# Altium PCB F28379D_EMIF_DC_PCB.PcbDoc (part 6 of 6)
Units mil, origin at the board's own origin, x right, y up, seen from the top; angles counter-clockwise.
Board outline 3000 x 1480 mil, 6 copper layers (Top Layer, Signal Layer 1, Signal Layer 2, Signal Layer 3, Signal Layer 4, Bottom Layer), stack 61.4 mil thick; 51 components, 68 nets, 414 pads, 205 vias.
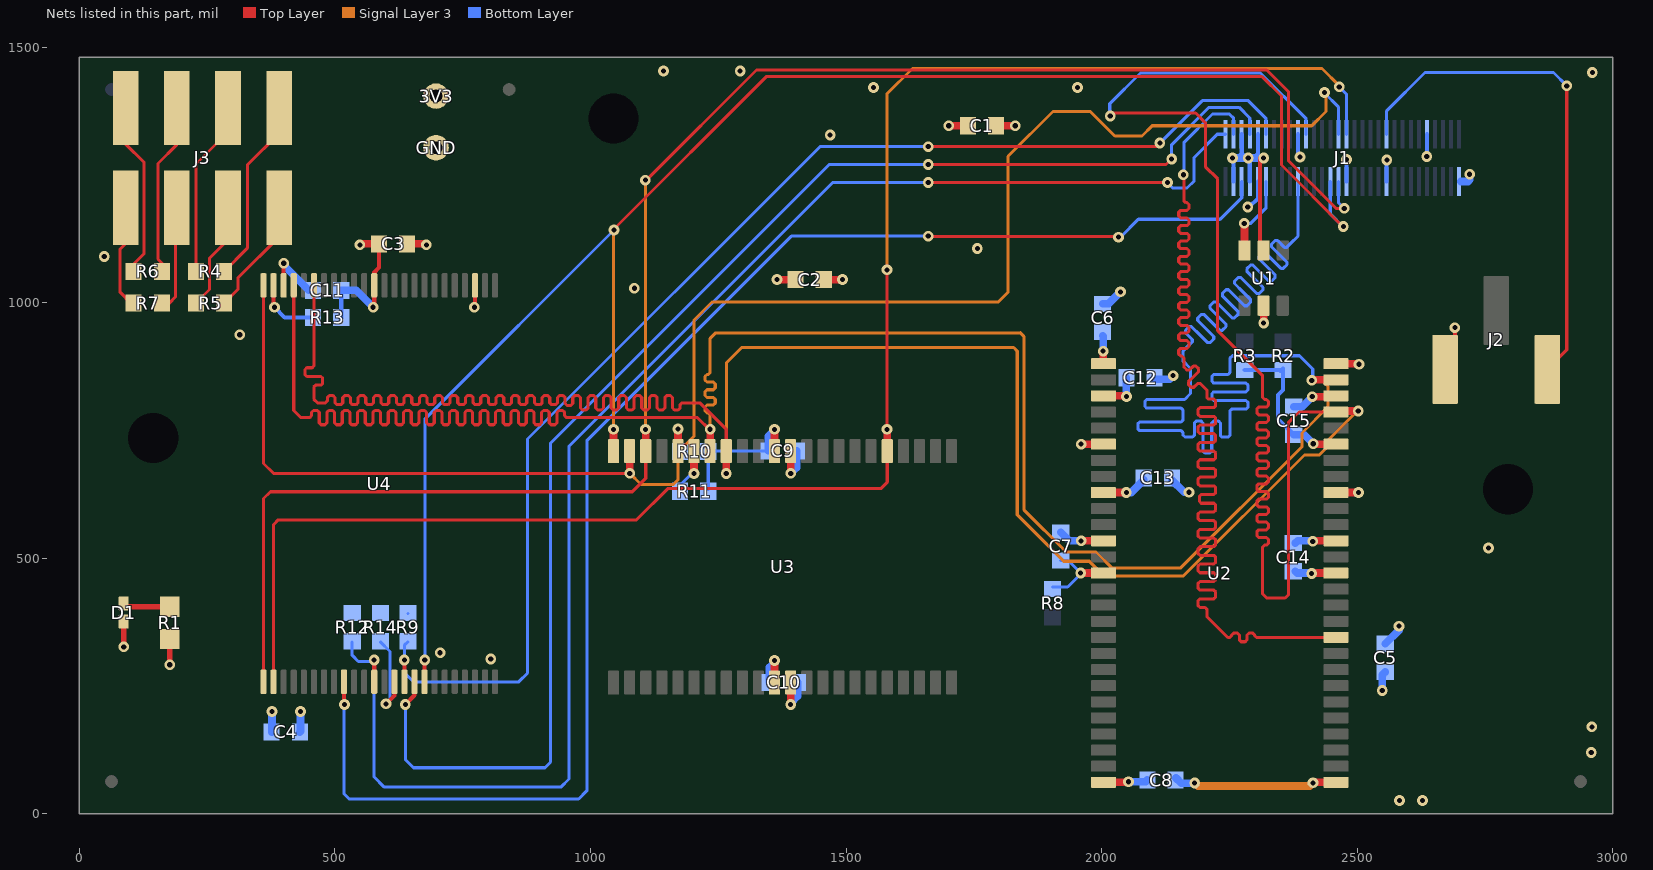
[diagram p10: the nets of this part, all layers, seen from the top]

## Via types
v1: diameter 21, hole 10, Top Layer to Bottom Layer, 204 vias
v2: diameter 20, hole 10, Top Layer to Bottom Layer, 1 vias

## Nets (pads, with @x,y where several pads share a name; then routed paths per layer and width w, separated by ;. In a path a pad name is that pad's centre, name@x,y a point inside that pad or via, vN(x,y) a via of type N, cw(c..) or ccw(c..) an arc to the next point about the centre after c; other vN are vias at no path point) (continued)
EM_D14: J1.40@2400.13,1329.26 U2.51 U3.37 U4.43 | length 6462.4
  Top Layer w6: U4.43@459.05,1033.8 459.05,967 459.05,875.9 455.65,872.5 445.25,872.5 441.85,869.1 441.85,858.9 445.25,855.5 459.05,855.5 472.85,855.5 476.25,852.1 476.25,841.9 472.85,838.5 462.45,838.5 459.05,835.1 459.05,821.5 459.05,813 459.05,811 466.05,804 478,804 481.75,804 485.5,807.75 485.5,814.25 489.25,818 496.75,818 500.5,814.25 500.5,804 504.23,800.26 511.77,800.26 515.5,804 515.5,814.25 519.25,818 526.75,818 530.5,814.25 530.5,804 534.23,800.26 541.77,800.26 545.5,804 545.5,814.25 549.25,818 556.75,818 560.5,814.25 560.5,804 564.23,800.26 571.77,800.26 575.5,804 575.5,814.25 579.25,818 586.75,818 590.5,814.25 590.5,804 594.23,800.26 601.77,800.26 605.5,804 605.5,814.25 609.25,818 616.75,818 620.5,814.25 620.5,804 624.23,800.26 631.77,800.26 635.5,804 635.5,814.25 639.25,818 646.75,818 650.5,814.25 650.5,804 654.23,800.26 661.77,800.26 665.5,804 665.5,814.25 669.25,818 676.75,818 680.5,814.25 680.5,804 684.23,800.26 691.77,800.26 695.5,804 695.5,814.25 699.25,818 706.75,818 710.5,814.25 710.5,804 714.23,800.26 721.77,800.26 725.5,804 725.5,814.25 729.25,818 736.75,818 740.5,814.25 740.5,804 744.23,800.26 751.77,800.26 755.5,804 755.5,814.25 759.25,818 766.75,818 770.5,814.25 770.5,804 774.23,800.26 781.77,800.26 785.5,804 785.5,814.25 789.25,818 796.75,818 800.5,814.25 800.5,804 804.23,800.26 811.77,800.26 815.5,804 815.5,814.25 819.25,818 826.75,818 830.5,814.25 830.5,804 834.23,800.26 841.77,800.26 845.5,804 845.5,814.25 849.25,818 856.75,818 860.5,814.25 860.5,804 864.23,800.26 871.77,800.26 875.5,804 875.5,814.25 879.25,818 886.75,818 890.5,814.25 890.5,804 894.23,800.26 901.77,800.26 905.5,804 905.5,814.25 909.25,818 916.75,818 920.5,814.25 920.5,804 924.23,800.26 931.77,800.26 935.5,804 935.5,814.25 939.25,818 946.75,818 950.5,814.25 950.5,804 950.5,802.58 954.25,798.83 961.75,798.83 965.5,802.58 965.5,804 965.5,814.25 969.25,818 976.75,818 980.5,814.25 980.5,804 980.5,793.75 984.25,790 991.75,790 995.5,793.75 995.5,804 995.5,814.25 999.25,818 1006.75,818 1010.5,814.25 1010.5,804 1010.5,793.75 1014.25,790 1021.75,790 1025.5,793.75 1025.5,804 1025.5,814.25 1029.25,818 1036.75,818 1040.5,814.25 1040.5,804 1040.5,793.75 1044.25,790 1051.75,790 1055.5,793.75 1055.5,804 1055.5,814.25 1059.25,818 1066.75,818 1070.5,814.25 1070.5,804 1070.5,793.75 1074.25,790 1081.75,790 1085.5,793.75 1085.5,804 1085.5,814.25 1089.25,818 1096.75,818 1100.5,814.25 1100.5,804 1100.5,793.75 1104.25,790 1111.75,790 1115.5,793.75 1115.5,804 1115.5,814.25 1119.25,818 1126.75,818 1130.5,814.25 1130.5,804 1130.5,793.75 1134.25,790 1141.75,790 1145.5,793.75 1145.5,804 1145.5,814.25 1149.25,818 1156.75,818 1160.5,814.25 1160.5,804 1160.5,793.75 1164.25,790 1171.75,790 1175.5,793.75 1175.5,800.25 1179.25,804 1206,804 1214,804 1265.76,752.24 U3.37@1265.76,709.38 ; v1@2016,1366 2021,1371 2184,1371 2203,1352 2203,1266 2227,1242 2227,945 2315,857 2315,818 2315,814.25 2318.75,810.5 2322.5,810.5 2326.25,806.75 2326.25,799.25 2322.5,795.5 2315,795.5 2307.5,795.5 2303.75,791.75 2303.75,784.25 2307.5,780.5 2315,780.5 2322.5,780.5 2326.25,776.75 2326.25,769.25 2322.5,765.5 2315,765.5 2307.5,765.5 2303.75,761.75 2303.75,754.25 2307.5,750.5 2315,750.5 2322.5,750.5 2326.25,746.75 2326.25,739.25 2322.5,735.5 2315,735.5 2307.5,735.5 2303.75,731.75 2303.75,724.25 2307.5,720.5 2315,720.5 2322.5,720.5 2326.25,716.75 2326.25,709.25 2322.5,705.5 2315,705.5 2307.5,705.5 2303.75,701.75 2303.75,694.25 2307.5,690.5 2315,690.5 2322.5,690.5 2326.25,686.75 2326.25,679.25 2322.5,675.5 2315,675.5 2307.5,675.5 2303.75,671.75 2303.75,664.25 2307.5,660.5 2315,660.5 2322.5,660.5 2326.25,656.75 2326.25,649.25 2322.5,645.5 2315,645.5 2307.5,645.5 2303.75,641.75 2303.75,634.25 2307.5,630.5 2315,630.5 2322.5,630.5 2326.25,626.75 2326.25,619.25 2322.5,615.5 2315,615.5 2307.5,615.5 2303.75,611.75 2303.75,604.25 2307.5,600.5 2315,600.5 2322.5,600.5 2326.25,596.75 2326.25,589.25 2322.5,585.5 2315,585.5 2307.5,585.5 2303.75,581.75 2303.75,574.25 2307.5,570.5 2315,570.5 2322.5,570.5 2326.25,566.75 2326.25,559.25 2322.5,555.5 2315,555.5 2307.5,555.5 2303.75,551.75 2303.75,544.25 2307.5,540.5 2315,540.5 2322.5,540.5 2326.25,536.75 2326.25,529.25 2322.5,525.5 2318.75,525.5 2315,521.75 2315,445 2315,430 2323,422 2359,422 2366,429 2366,765.92 2386.04,785.96 U2.51@2458.36,785.96
  Top Layer w15: v1(1265.76,665.76) U3.37@1265.76,709.38 ; U2.51@2458.36,785.96 2460.4,788 v1@2500,788
  Signal Layer 3 w6: v1@1265.76,674.76 1266,675 1266,882 1296,912 1828,912 1835,905 1835,585 1926,494 1976,494 2005,465 2160,465 2397,702 2426,702 2439,715 2439,727 v1@2500,788
  Bottom Layer w6: v1@2016,1366 2016,1389 2076,1449 2311,1449 2400.13,1359.87 J1.40@2400.13,1329.26
  other v1: 2502,788 2017,1365
EM_D15: J1.41@2384.39,1236.74 U2.53 U3.38 U4.45 | length 6511.9
  Top Layer w6: U4.45@419.68,1033.8 419.68,789 433.68,775 447,775 450.75,775 454.5,778.75 454.5,785.25 458.25,789 465.75,789 469.5,785.25 469.5,775 469.5,764.75 473.25,761 480.75,761 484.5,764.75 484.5,775 484.5,785.25 488.25,789 495.75,789 499.5,785.25 499.5,775 499.5,764.75 503.25,761 510.75,761 514.5,764.75 514.5,775 514.5,785.25 518.25,789 525.75,789 529.5,785.25 529.5,775 529.5,764.75 533.25,761 540.75,761 544.5,764.75 544.5,775 544.5,785.25 548.25,789 555.75,789 559.5,785.25 559.5,775 559.5,764.75 563.25,761 570.75,761 574.5,764.75 574.5,775 574.5,785.25 578.25,789 585.75,789 589.5,785.25 589.5,775 589.5,764.75 593.25,761 600.75,761 604.5,764.75 604.5,775 604.5,785.25 608.25,789 615.75,789 619.5,785.25 619.5,775 619.5,764.75 623.25,761 630.75,761 634.5,764.75 634.5,775 634.5,785.25 638.25,789 645.75,789 649.5,785.25 649.5,775 649.5,764.75 653.25,761 660.75,761 664.5,764.75 664.5,775 664.5,785.25 668.25,789 675.75,789 679.5,785.25 679.5,775 679.5,764.75 683.25,761 690.75,761 694.5,764.75 694.5,775 694.5,785.25 698.25,789 705.75,789 709.5,785.25 709.5,775 709.5,764.75 713.25,761 720.75,761 724.5,764.75 724.5,775 724.5,785.25 728.25,789 735.75,789 739.5,785.25 739.5,775 739.5,764.75 743.25,761 750.75,761 754.5,764.75 754.5,775 754.5,785.25 758.25,789 765.75,789 769.5,785.25 769.5,775 769.5,764.75 773.25,761 780.75,761 784.5,764.75 784.5,775 784.5,785.25 788.25,789 795.75,789 799.5,785.25 799.5,775 799.5,764.75 803.25,761 810.75,761 814.5,764.75 814.5,775 814.5,785.25 818.25,789 825.75,789 829.5,785.25 829.5,775 829.5,764.75 833.25,761 840.75,761 844.5,764.75 844.5,775 844.5,785.25 848.25,789 855.75,789 859.5,785.25 859.5,775 859.5,764.75 863.25,761 870.75,761 874.5,764.75 874.5,775 874.5,785.25 878.25,789 885.75,789 889.5,785.25 889.5,775 889.5,764.75 893.25,761 900.75,761 904.5,764.75 904.5,775 904.5,785.25 908.25,789 915.75,789 919.5,785.25 919.5,775 919.5,764.75 923.25,761 930.75,761 934.5,764.75 934.5,775 934.5,785.25 938.25,789 945.75,789 949.5,785.25 949.5,778.75 953.25,775 1026,775 1209.54,775 v1@1234.27,750.27
  Top Layer w15: U3.38@1234.27,709.38 v1@1234.27,744.27 ; v1(2411.05,847.95) 2412.05,848.95 U2.53@2458.36,848.95
  Signal Layer 3 w6: v1@1234.27,744.27 v1(1234.27,752.27) 1234.27,777 1234.27,780.75 1230.52,784.5 1228.02,784.5 1224.27,788.25 1224.27,795.75 1228.02,799.5 1234.27,799.5 1240.52,799.5 1244.27,803.25 1244.27,810.75 1240.52,814.5 1234.27,814.5 1228.02,814.5 1224.27,818.25 1224.27,825.75 1228.02,829.5 1234.27,829.5 1240.52,829.5 1244.27,833.25 1244.27,840.75 1240.52,844.5 1234.27,844.5 1228.02,844.5 1224.27,848.25 1224.27,855.75 1228.02,859.5 1230.52,859.5 1234.27,863.25 1234.27,918 1234.27,930 1245,940.73 1840.73,940.73 1841,941 1848,934 1848,595 1931,512 1989,512 2020,481 2155,481 2392,718 2392,745 2443,796 2443,836 2430.05,848.95 2412.05,848.95 v1(2411.05,847.95)
  Bottom Layer w6: J1.41@2384.39,1236.74 2384.39,1130 2369.19,1114.81 2362.42,1108.03 2357.61,1108.03 2344.33,1121.32 2339.52,1121.32 2332.31,1114.11 2332.31,1109.3 2347.99,1093.61 2362.67,1078.93 2362.67,1074.12 2355.46,1066.91 2350.65,1066.91 2335.97,1081.59 2320.29,1097.28 2315.48,1097.28 2308.26,1090.06 2308.26,1085.26 2323.95,1069.57 2339.64,1053.88 2339.64,1049.07 2332.43,1041.86 2327.62,1041.86 2311.93,1057.55 2296.24,1073.24 2291.44,1073.24 2284.22,1066.02 2284.22,1061.21 2299.91,1045.53 2315.6,1029.84 2315.6,1025.03 2308.39,1017.82 2303.58,1017.82 2287.89,1033.5 2272.2,1049.19 2267.39,1049.19 2260.18,1041.98 2260.18,1037.17 2275.87,1021.48 2291.56,1005.8 2291.56,1000.99 2284.35,993.77 2279.54,993.77 2263.85,1009.46 2248.16,1025.15 2243.35,1025.15 2236.14,1017.94 2236.14,1013.13 2251.83,997.44 2267.09,982.18 2267.09,977.37 2259.88,970.16 2255.07,970.16 2239.81,985.42 2224.12,1001.11 2219.31,1001.11 2212.1,993.9 2212.1,989.09 2227.79,973.4 2243.48,957.71 2243.48,952.9 2236.26,945.69 2231.45,945.69 2215.77,961.38 2200.08,977.07 2195.27,977.07 2188.06,969.86 2188.06,965.05 2203.74,949.36 2219.43,933.67 2219.43,928.86 2212.22,921.65 2207.41,921.65 2191.72,937.34 2176.04,953.03 2171.23,953.03 2164.01,945.81 2164.01,941.01 2177.3,927.72 2177.3,922.91 2173.69,919.31 2159,904.61 2159,886 2174,871 2174,822 2162.5,810.5 2158.5,810.5 2088.4,810.5 2085,807.1 2085,796.9 2088.4,793.5 2155.6,793.5 2159,790.1 2159,785 2159,774 2159,769.9 2155.6,766.5 2074.4,766.5 2071,763.1 2071,752.9 2074.4,749.5 2155.6,749.5 2159,746.1 2159,741 2163,737 2173,737 2178.1,737 2181.5,740.4 2181.5,764.6 2184.9,768 2195.1,768 2198.5,764.6 2198.5,737 2198.5,709.4 2201.9,706 2212.1,706 2215.5,709.4 2215.5,737 2215.5,764.6 2218.9,768 2229.1,768 2232.5,764.6 2232.5,739.5 2235,737 2248,737 2251,740 2251,783 2251,788.1 2254.4,791.5 2282.6,791.5 2286,794.9 2286,805.1 2282.6,808.5 2251,808.5 2219.4,808.5 2216,811.9 2216,822.1 2219.4,825.5 2251,825.5 2282.6,825.5 2286,828.9 2286,839.1 2282.6,842.5 2251,842.5 2219.4,842.5 2216,845.9 2216,856.1 2219.4,859.5 2247.6,859.5 2251,862.9 2251,876.5 2251,885 2251,891 2256,896 2387,896 2413.05,869.95 v1@2413.05,849.95 ; v1@2409.79,845.69 2413.05,848.95 v1@2413.05,849.95 ; v1(2411.05,847.95) v1@2413.05,849.95
EM_SDCKE: J1.58@2258.4,1329.26 U2.37 | length 2486.2
  Top Layer w6: v1(2160,1250) 2161,1249 2161,1203 2161,1199.25 2164.75,1195.5 2167.25,1195.5 2171,1191.75 2171,1184.25 2167.25,1180.5 2161,1180.5 2154.75,1180.5 2151,1176.75 2151,1169.25 2154.75,1165.5 2161,1165.5 2167.25,1165.5 2171,1161.75 2171,1154.25 2167.25,1150.5 2161,1150.5 2154.75,1150.5 2151,1146.75 2151,1139.25 2154.75,1135.5 2161,1135.5 2167.25,1135.5 2171,1131.75 2171,1124.25 2167.25,1120.5 2161,1120.5 2154.75,1120.5 2151,1116.75 2151,1109.25 2154.75,1105.5 2161,1105.5 2167.25,1105.5 2171,1101.75 2171,1094.25 2167.25,1090.5 2161,1090.5 2154.75,1090.5 2151,1086.75 2151,1079.25 2154.75,1075.5 2161,1075.5 2167.25,1075.5 2171,1071.75 2171,1064.25 2167.25,1060.5 2161,1060.5 2154.75,1060.5 2151,1056.75 2151,1049.25 2154.75,1045.5 2161,1045.5 2167.25,1045.5 2171,1041.75 2171,1034.25 2167.25,1030.5 2161,1030.5 2154.75,1030.5 2151,1026.75 2151,1019.25 2154.75,1015.5 2161,1015.5 2167.25,1015.5 2171,1011.75 2171,1004.25 2167.25,1000.5 2161,1000.5 2154.75,1000.5 2151,996.75 2151,989.25 2154.75,985.5 2161,985.5 2167.25,985.5 2171,981.75 2171,974.25 2167.25,970.5 2161,970.5 2154.75,970.5 2151,966.75 2151,959.25 2154.75,955.5 2161,955.5 2167.25,955.5 2171,951.75 2171,944.25 2167.25,940.5 2161,940.5 2154.75,940.5 2151,936.75 2151,929.25 2154.75,925.5 2161,925.5 2167.25,925.5 2171,921.75 2171,914.25 2167.25,910.5 2161,910.5 2154.75,910.5 2151,906.75 2151,899.25 2154.75,895.5 2157.25,895.5 2161,891.75 2161,880.5 2161,877 2161,874 2164,871 2166.65,868.35 2171.95,868.35 2179.38,875.77 2184.68,875.77 2189.99,870.47 2189.99,865.17 2179.91,855.09 2169.83,845.01 2169.83,839.71 2175.14,834.41 2180.44,834.41 2187.86,841.83 2193.17,841.83 2199.5,835.5 2206,829 2206,814 2208.5,811.5 2219.67,811.5 2223.07,808.1 2223.07,797.9 2219.67,794.5 2206,794.5 2192.33,794.5 2188.93,791.1 2188.93,780.9 2192.33,777.5 2206,777.5 2219.67,777.5 2223.07,774.1 2223.07,763.9 2219.67,760.5 2206,760.5 2192.33,760.5 2188.93,757.1 2188.93,746.9 2192.33,743.5 2206,743.5 2219.67,743.5 2223.07,740.1 2223.07,729.9 2219.67,726.5 2206,726.5 2192.33,726.5 2188.93,723.1 2188.93,712.9 2192.33,709.5 2206,709.5 2219.67,709.5 2223.07,706.1 2223.07,695.9 2219.67,692.5 2206,692.5 2192.33,692.5 2188.93,689.1 2188.93,678.9 2192.33,675.5 2206,675.5 2219.67,675.5 2223.07,672.1 2223.07,661.9 2219.67,658.5 2206,658.5 2192.33,658.5 2188.93,655.1 2188.93,644.9 2192.33,641.5 2206,641.5 2219.67,641.5 2223.07,638.1 2223.07,627.9 2219.67,624.5 2206,624.5 2194.79,624.5 2191.39,621.1 2191.39,610.9 2194.79,607.5 2206,607.5 2219.67,607.5 2223.07,604.1 2223.07,593.9 2219.67,590.5 2206,590.5 2192.33,590.5 2188.93,587.1 2188.93,576.9 2192.33,573.5 2206,573.5 2219.67,573.5 2223.07,570.1 2223.07,559.9 2219.67,556.5 2206,556.5 2192.33,556.5 2188.93,553.1 2188.93,542.9 2192.33,539.5 2206,539.5 2219.67,539.5 2223.07,536.1 2223.07,525.9 2219.67,522.5 2206,522.5 2192.33,522.5 2188.93,519.1 2188.93,508.9 2192.33,505.5 2206,505.5 2219.67,505.5 2223.07,502.1 2223.07,491.9 2219.67,488.5 2206,488.5 2192.33,488.5 2188.93,485.1 2188.93,474.9 2192.33,471.5 2206,471.5 2219.67,471.5 2223.07,468.1 2223.07,457.9 2219.67,454.5 2206,454.5 2192.33,454.5 2188.93,451.1 2188.93,440.9 2192.33,437.5 2206,437.5 2219.67,437.5 2223.07,434.1 2223.07,423.9 2219.67,420.5 2206,420.5 2192.33,420.5 2188.93,417.1 2188.93,406.9 2192.33,403.5 2202.6,403.5 2206,400.1 2206,395 2206,386.02 2247,345.02 2250.75,345.02 2254.5,348.77 2254.5,349.7 2258.25,353.45 2265.75,353.45 2269.5,349.7 2269.5,345.02 2269.5,340.33 2273.25,336.58 2280.75,336.58 2284.5,340.33 2284.5,345.02 2284.5,349.7 2288.25,353.45 2295.75,353.45 2299.5,349.7 2299.5,348.52 2303,345.02 U2.37@2458.36,345.02
  Bottom Layer w6: v1(2160,1250) 2161,1251 2161,1313 2217,1369 2250,1369 2258.4,1360.6 J1.58@2258.4,1329.26
EM_WAIT: J1.50@2321.39,1329.26 R9.1 U4.15 | length 2580.9
  Top Layer w6: v1(1661,1305) 2107,1305 v1(2114,1312)
  Top Layer w8: v1@636,298 636.21,297.79 U4.15@636.21,258.2
  Bottom Layer w6: R9.1@643,336.44 636,329.44 v1(636,301) 636,276 654,258 860,258 877,275 877,733 1449,1305 v1(1661,1305) ; v1(2114,1312) 2197,1395 2287,1395 2321.39,1360.61 J1.50@2321.39,1329.26
GND: C1.2 C2.2 C3.2 C4.2 C5.2 C6.2 C7.2 C8.2 C9.2 C10.2 C11.2 C12.2 C13.2 C14.2 C15.2 D1.2 GND.1 J1.1@2699.35,1236.74 J1.10@2636.35,1329.26 J1.19@2557.61,1236.74 J1.29@2478.87,1236.74 J1.42@2384.39,1329.26 J1.51@2305.65,1236.74 J2.3 R10.1 R11.1 U1.2 U2.6 U2.12 U2.28 U2.41 U2.46 U2.52 U2.54 U3.12 U3.34 U4.27 U4.46 | length 1948.3
  Top Layer w8: U4.46@399.99,1033.8 v1@399.99,1075.99 ; v1@773,995 v1@774.01,996.01 ; v1@774.01,994.01 v1@774.01,996.01 ; U4.27@774.01,1033.8 v1@774.01,996.01 ; J2.3@2672,869.52 2691,888.52 v1(2691,951)
  Top Layer w10: v1@87,328.5 D1.2@87,375.78
  Top Layer w15: C3.2@641.56,1107 C3.2@645.56,1111 ; C3.2@641.56,1115 677,1115 v1(679,1113) ; v1@1360,745 1360.25,744.75 U3.34@1360.25,709.38 ; v1(1365,1045) C2.2@1401.44,1045 ; v1@1391.75,221.75 U3.12@1391.75,256.62 ; v1@1710,1346 C1.2@1738.44,1346 ; v1@1963.99,533.99 U2.12@2003.64,533.99 ; v1@1964.03,722.97 U2.6@2003.64,722.97 ; v1@2317,961 U1.2@2317,993.87 ; v1@2411,471 U2.41@2458.36,471 ; v1@2416.55,61.55 U2.28@2458.36,61.55 ; v1@2420,816 2456.91,816 U2.52@2458.36,817.46 ; U2.46@2458.36,628.48 v1@2498.48,628.48 ; U2.54@2458.36,880.45 v1@2500.45,880.45
  Signal Layer 3 w15: v1(2182,60) 2183,60 2188.5,54.5 2407.5,54.5 v1(2413.55,60.55)
  Bottom Layer w6: R11.1@1230.56,634 R10.1@1230.56,709 1231.56,710 C9.2@1348.44,710
  Bottom Layer w8: v1@2286,1188 2289.65,1188 2305.65,1204 J1.51@2305.65,1236.74 ; v1@2384,1285 2384.39,1285.39 v1@2384.39,1287.61 ; J1.42@2384.39,1329.26 v1@2384.39,1287.61 ; v1@2386,1286 v1@2384.39,1287.61 ; v1@2478,1279 2478.87,1278.13 J1.29@2478.87,1236.74 ; v1@2557,1278 2557.61,1277.39 J1.19@2557.61,1236.74 ; v1(2636,1286) 2636.35,1286.35 J1.10@2636.35,1329.26
  Bottom Layer w15: C4.2@376.44,160 377,160.56 v1(377,200) ; v1@400,1073 449,1024 C11.2@457.44,1024 ; C9.2@1348.44,710 1348.44,738.44 v1@1360,750 ; v1@1391.75,216.75 1405.56,230.56 C10.2@1405.56,257 ; C7.2@1920,550.56 1936.57,533.99 v1(1959.99,533.99) v1@1963.99,533.99 ; C6.2@2002,997.56 2013.56,997.56 v1(2037,1021) ; C12.2@2103.56,850 v1@2133,850 ; C13.2@2137.56,653 2161.56,629 v1(2171,629) ; C8.2@2145.56,70 2155.56,60 v1(2182,60) ; C15.2@2376,796.56 2392.56,796.56 v1(2412,816) ; C14.2@2379,474.44 2382.44,471 v1@2411,471 ; v1(2549,241) 2549,271.44 C5.2@2555,277.44 ; J1.1@2703,1236.74 2716.74,1236.74 2720,1240 v1(2720,1251)
  other v1: 2628,26 2959,170 1391.75,213.75 805,303 87,326.5 2411,470 2502.48,628.48 1960,723 1360,752 2140,857 2503.45,879.45 2317,960 773,991 400,1077 1757,1106 2286,1187 2558,1279 2479,1280 2388,1285 1701,1346 1554,1421 1953,1421 1143,1453
GPIO_/RESET: J1.60@2242.65,1329.26 R12.2 U4.12 | length 2971.2
  Top Layer w6: v1@1661,1228 v1@1668,1235 ; v1(1661,1235) v1@1668,1235 ; v1(2129,1235) v1@1668,1235
  Top Layer w8: v1@577,298 577.16,297.84 U4.12@577.16,258.2
  Bottom Layer w6: R12.2@534,336.44 534,310 546,298 577,298 577,72 597,52 942,52 958,68 958,719 1474,1235 v1(1661,1235) ; v1(2129,1235) 2129,1234 2139,1224 2167,1224 2181,1238 2181,1284 2226.26,1329.26 J1.60@2242.65,1329.26
  other v1: 577,301
GPIO_A13: J1.30@2478.87,1329.26 U3.27 U4.2 | length 3320.6
  Top Layer w6: U4.2@380.31,258.2 380.31,566 389.31,575 1090,575 1151,636 1568,636 1580.72,648.72 U3.27@1580.72,709.38 ; v1@1580,749 v1(1580,752) v1(1580,1064)
  Top Layer w15: U3.27@1580.72,709.38 v1@1580.72,744.72
  Signal Layer 3 w6: v1(1580,1064) 1580,1408 1630,1458 2431,1458 v1@2465,1424 ; v1(2465,1422) v1@2465,1424 ; v1@2467,1422 v1@2465,1424
  Bottom Layer w6: v1(2465,1422) 2478.87,1408.13 J1.30@2478.87,1329.26
GPIO_A14: J1.31@2463.13,1236.74 U3.42 U4.1 | length 3412.9
  Top Layer w6: U4.1@360.62,258.2 360.62,616.62 374,630 1082,630 1108.28,656.28 U3.42@1108.28,709.38 ; v1(1107.5,1239.5) 1109.5,1239.5 1325,1455 2323,1455 2366,1412 2366,1277 2458.62,1184.38 v1(2474.62,1184.38)
  Top Layer w15: v1@1108,750 1108.28,749.72 U3.42@1108.28,709.38
  Signal Layer 3 w6: v1(1107.5,1239.5) 1108,1239 v1@1108,1238 ; v1@1108,750 v1(1108,752) v1@1108,1238 ; v1@1109.5,1239.5 v1@1108,1238
  Bottom Layer w6: J1.31@2463.13,1236.74 2463.13,1195.87 v1(2474.62,1184.38)
GPIO_A15: J1.32@2463.13,1329.26 U3.43 U4.48 | length 3277.1
  Top Layer w6: U4.48@360.62,1033.8 360.62,685.38 380,666 v1(1077,666)
  Top Layer w15: v1@1076.79,670 U3.43@1076.79,709.38
  Signal Layer 3 w6: v1(1077,666) 1099,644 1162,644 1171,653 1171,707 1203,739 1203,966 1238,1001 1798,1001 1817,1020 1817,1286 1905,1374 1978,1374 2026,1326 2079,1326 2099,1346 2411,1346 2439,1374 2439,1408 v1(2436,1411)
  Bottom Layer w6: v1(2436,1411) 2436,1410 2463.13,1382.87 J1.32@2463.13,1329.26
GPIO_A16: J1.33@2447.38,1236.74 U3.44 U4.17 | length 3331.4
  Top Layer w6: v1@1044,1142 v1@1046,1144 ; v1(1046,1142) v1@1046,1144 ; v1@2474,1147 2352,1269 2352,1404 2314,1442 1344,1442 v1@1046,1144
  Top Layer w8: U4.17@675.58,258.2 675.58,300.58 v1(676,301)
  Top Layer w15: U3.44@1045.29,709.38 v1@1045.29,750
  Signal Layer 3 w6: v1@1045.29,750 v1(1045.29,752) 1045.29,1141.29 v1(1046,1142)
  Bottom Layer w6: v1@676,298 v1(676,301) 676,772 v1(1046,1142) ; J1.33@2447.38,1236.74 2447.38,1173.62 v1@2474,1147
  other v1: 2473,1149
GPIO_A17: J1.54@2289.9,1329.26 U4.16 | length 2777.7
  Top Layer w6: v1(1661,1270) 2126,1270 v1(2137,1281)
  Top Layer w8: v1(638,214) 655.9,231.9 U4.16@655.9,258.2
  Bottom Layer w6: v1@638,216 v1(638,214) 638,106 654,90 911,90 922,101 922,725 1467,1270 v1(1661,1270) ; v1(2137,1281) 2137,1309 2210,1382 2269,1382 2289.9,1361.1 J1.54@2289.9,1329.26
GPIO_A18: J1.55@2274.15,1236.74 U4.9 | length 2900.4
  Top Layer w6: v1(1661,1130) 1662,1129 v1@2033,1129
  Top Layer w8: v1@518,218 518.1,218.1 U4.9@518.1,258.2
  Bottom Layer w6: v1@518,218 518,39 528,29 977,29 993,45 993,730 1393,1130 v1(1661,1130) ; v1@2033,1129 2038,1129 2072,1163 2232,1163 2274.15,1205.15 J1.55@2274.15,1236.74
  other v1: 519,214 2033,1128
GPIO_CS_MUX: J1.49@2321.39,1236.74 U1.6 | length 160
  Top Layer w15: v1(2279,1155) 2279.6,1154.4 U1.6@2279.6,1102.13
  Bottom Layer w6: v1(2279,1155) 2292,1155 2321.39,1184.39 J1.49@2321.39,1236.74
GPIO_EM_A12: J1.20@2557.61,1329.26 J2.1 | length 1010.2
  Top Layer w6: J2.1@2872,869.52 2910,907.52 v1(2910,1424)
  Bottom Layer w6: J1.20@2557.61,1329.26 2557.61,1375 2632.61,1450 2884,1450 v1(2910,1424)
NetD1_1: D1.1 R1.1 | length 83.8
  Top Layer w10: D1.1@93.22,404.99 R1.1@177,404.99
NetJ3_1: J3.1 R4.2 | length 363.9
  Top Layer w6: R4.2@283.56,1061 329,1106.44 329,1269 391,1331 J3.1@391,1380.44
NetJ3_2: J3.2 R5.1 | length 231.1
  Top Layer w6: R5.1@283.56,999 311,1026.44 311,1049 391,1129 J3.2@391,1185.56
NetJ3_3: J3.3 R4.1 | length 345.4
  Top Layer w6: R4.1@228.44,1061 228.44,1271 291,1333.56 J3.3@291,1380.44
NetJ3_4: J3.4 R5.2 | length 212.5
  Top Layer w6: R5.2@228.44,999 255,1025.56 255,1087 291,1123 J3.4@291,1185.56
NetJ3_5: J3.5 R6.2 | length 337.9
  Top Layer w6: R6.2@161.56,1061 161.56,1077.44 154,1085 154,1272 191,1309 J3.5@191,1380.44
NetJ3_6: J3.6 R7.1 | length 207.2
  Top Layer w6: R7.1@161.56,999 176,999 188,1011 188,1182.56 J3.6@191,1185.56
NetJ3_7: J3.7 R6.1 | length 342.9
  Top Layer w6: J3.7@91,1380.44 91,1310 127,1274 127,1096 106.44,1075.44 R6.1@106.44,1061
NetJ3_8: J3.8 R7.2 | length 205.3
  Top Layer w6: J3.8@91,1185.56 91,1116 80,1105 80,1020 101,999 R7.2@106.44,999
NetR10_2: R10.2 U3.40 | length 85.8
  Top Layer w15: U3.40@1171.28,709.38 v1(1171.28,752.72)
  Bottom Layer w6: v1@1171.28,749.72 1171.28,713.16 R10.2@1175.44,709
NetR11_2: R11.2 U3.39 | length 90.7
  Top Layer w15: v1(1202.77,665.77) U3.39@1202.77,709.38
  Bottom Layer w6: R11.2@1175.44,634 1175.44,642.44 v1@1202.77,669.77
NetR13_2: R13.2 U4.47 | length 130.1
  Top Layer w8: U4.47@380.31,1033.8 380.31,992.69 v1(382,991)
  Bottom Layer w8: v1@381,994 v1@383,992 ; v1(382,991) 402,971 R13.2@457.44,971
NetR14_2: R14.2 U4.14 | length 182.7
  Top Layer w8: v1(600,215) 616.53,231.53 U4.14@616.53,258.2
  Bottom Layer w6: R14.2@589,336.44 608,317.44 608,223 v1(600,215)
VCC_3V3: 3V3.1 C1.1 C2.1 C3.1 C4.1 C5.1 C6.1 C7.1 C8.1 C9.1 C10.1 C11.1 C12.1 C13.1 C14.1 C15.1 J1.52@2305.65,1329.26 J1.53@2289.9,1236.74 J1.56@2274.15,1329.26 J1.57@2258.4,1236.74 R1.2 R2.2 R3.2 R8.2 R9.2 R12.1 R13.1 R14.1 U1.5 U2.1 U2.3 U2.9 U2.14 U2.27 U2.43 U2.49 U3.11 U3.33 U4.37 | length 1999.5
  Top Layer w8: v1(575,991) 577.16,993.16 U4.37@577.16,1033.8 577.16,1059.16 586.44,1068.44 C3.1@586.44,1107 ; v1@2310,1283 2310,1109.13 U1.5@2317,1102.13
  Top Layer w10: v1(177,291.5) R1.2@177,342
  Top Layer w15: v1(549,1113) 551,1115 C3.1@586.44,1115 ; C3.1@582.44,1111 C3.1@586.44,1107 ; U3.11@1360.25,256.62 v1@1360.25,291.75 ; U3.33@1391.75,709.38 1391.75,666.25 v1(1392,666) ; C2.1@1456.56,1045 v1(1493,1045) ; C1.1@1793.56,1346 v1@1822,1346 ; v1@1961,471 U2.14@2003.64,471 ; v1(2003,905) 2003,881.09 U2.1@2003.64,880.45 ; U2.27@2003.64,61.55 v1@2050.45,61.55 ; U2.9@2003.64,628.48 v1(2048.48,628.48) ; U2.3@2003.64,817.46 v1@2044.54,817.46 ; v1@2412.97,722.97 U2.49@2458.36,722.97 ; v1@2413.99,533.99 U2.43@2458.36,533.99
  Bottom Layer w6: R8.2@1904,443.5 1933.5,443.5 v1@1961,471 ; C7.1@1920,495.44 1934.56,495.44 v1(1959,471)
  Bottom Layer w8: R13.1@512.56,971 C11.1@512.56,1024 ; J1.57@2258.4,1236.74 v1@2258.4,1278.6 ; v1@2258.4,1275.4 2266,1283 2274.15,1291.15 2274.15,1291.85 ; J1.56@2274.15,1329.26 2274.15,1291.85 ; R3.2@2280,868.44 R2.2@2352,868.44 ; v1@2283,1283 2274.15,1291.85 ; J1.53@2289.9,1236.74 2289.9,1276.1 2305.65,1291.65 ; J1.52@2305.65,1329.26 2305.65,1289.35 v1@2312,1283 ; R2.2@2350,866.44 R2.2@2352,868.44 ; R2.2@2355,868.44 2355,829 2345,819 2345,772.44 C15.1@2376,741.44 ; R2.2@2355,871.44 R2.2@2352,868.44
  Bottom Layer w15: C4.1@431.56,160 433,161.44 v1(433,200) ; C11.1@512.56,1024 542,1024 v1(575,991) ; C10.1@1350.44,257 1350.44,286.94 v1@1360.25,296.75 ; v1(1392,666) 1403.56,677.56 C9.1@1403.56,710 ; v1@1960,472 v1@1961,471 ; C6.1@2002,935.44 2003,934.44 v1(2003,905) ; C12.1@2048.44,853 2048.44,816.56 v1(2048.54,816.46) ; v1(2048.48,628.48) 2057.92,628.48 C13.1@2082.44,653 ; v1@2050.45,61.55 2051,61 v1@2052.45,61 ; v1(2052.45,62.55) 2085.99,62.55 C8.1@2089.44,66 ; v1@2254,1283 2283,1283 v1@2312,1283 ; C15.1@2376,741.44 2396.5,741.44 v1(2413.97,723.97) ; C14.1@2379,529.56 2383.43,533.99 v1@2413.99,533.99 ; C5.1@2555,332.56 2582,359.56 v1(2582,367)
  other v1: 2583,26 2958,120 1360.25,299.75 706,315 2757,520 2412.99,532.99 1086,1028 49,1090 2256,1283 2287,1283 2317,1283 1469,1328 1831,1346 2960,1450 1293,1453
  other v2: 313.98,937.04
pads on no net: FID1.1 FID2.1 FID3.1 FID4.1 FID5.1 FID6.1 H1.1 H2.1 H3.1 J1.1@2699.35,1222.37 J1.2@2699.35,1343.63 J1.3@2683.6,1222.37 J1.4@2683.6,1343.63 J1.5@2667.85,1222.37 J1.6@2667.85,1343.63 J1.7@2652.1,1222.37 J1.8@2652.1,1343.63 J1.9@2636.35,1222.37 J1.10@2636.35,1343.63 J1.11@2620.61,1222.37 J1.12@2620.61,1343.63 J1.13@2604.86,1222.37 J1.14@2604.86,1343.63 J1.15@2589.11,1222.37 J1.16@2589.11,1343.63 J1.17@2573.36,1222.37 J1.18@2573.36,1343.63 J1.19@2557.61,1222.37 J1.20@2557.61,1343.63 J1.21@2541.87,1222.37 J1.22@2541.87,1343.63 J1.23@2526.12,1222.37 J1.24@2526.12,1343.63 J1.25@2510.37,1222.37 J1.26@2510.37,1343.63 J1.27@2494.62,1222.37 J1.28@2494.62,1343.63 J1.29@2478.87,1222.37 J1.30@2478.87,1343.63 J1.31@2463.13,1222.37 J1.32@2463.13,1343.63 J1.33@2447.38,1222.37 J1.34@2447.38,1343.63 J1.35@2431.63,1222.37 J1.36@2431.63,1343.63 J1.37@2415.88,1222.37 J1.38@2415.88,1343.63 J1.39@2400.13,1222.37 J1.40@2400.13,1343.63 J1.41@2384.39,1222.37 J1.42@2384.39,1343.63 J1.43@2368.64,1222.37 J1.44@2368.64,1343.63 J1.45@2352.89,1222.37 J1.46@2352.89,1343.63 J1.47@2337.14,1222.37 J1.48@2337.14,1343.63 J1.49@2321.39,1222.37 J1.50@2321.39,1343.63 J1.51@2305.65,1222.37 J1.52@2305.65,1343.63 J1.53@2289.9,1222.37 J1.54@2289.9,1343.63 J1.55@2274.15,1222.37 J1.56@2274.15,1343.63 J1.57@2258.4,1222.37 J1.58@2258.4,1343.63 J1.59@2242.65,1222.37 J1.60@2242.65,1343.63 U2.40 U3.28 U4.10 U4.13

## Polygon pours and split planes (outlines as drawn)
GND on Signal Layer 1 "GND-2" (solid, remove dead copper, pour order 2): 0,-10 3000,-10 3000,1490 0,1490 0,-10
GND on Signal Layer 4 "GND-5" (solid, remove dead copper, pour order 7): 0,-10 3000,-10 3000,1490 0,1490 0,-10
VCC_3V3 on Signal Layer 2 "VCC_3V3-3" (solid, remove dead copper, pour order 6): 0,-10 3000,-10 3000,1490 0,1490 0,-10
VCC_3V3 on Top Layer "Top 3V3" (solid, remove dead copper, pour order 0): 0,-10 3000,-10 3000,1490 0,1490
GND on Signal Layer 3 "Sig 3 GND" (solid, remove dead copper, pour order 4): 0,-10 3000,-10 3000,1490 0,1490
VCC_3V3 on Bottom Layer "Bot 3V3" (solid, remove dead copper, pour order 8): 0,-10 3000,-10 3000,1490 0,1490

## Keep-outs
Keep-Out Layer:
  text ".Layer_Name" at 577,-868.49 h60

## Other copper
Top Layer:
  pour cut-out: 2841.42,776.1 2841.52,776 2920,776 2920,957 2910,947 2838,947
  pour cut-out: 440,1110 440,984 430,974 427.43,976.57 305,976.57 305,1104 311,1110
  pour cut-out: 25.49,1464.51 25.98,1465 448,1465 448,1094.66 446.83,1093.48 429.61,1110.71 25.49,1110.71
  pour cut-out: 88,1108 89,1107 305,1107 305,976.57 306.31,975.27 83.69,975.27
  pour cut-out: 1536.8,996.21 1536.8,1003.49 1421.38,1003.49 1420.16,1002.27 1426,996.43 1426,994 1534.59,994
  pour cut-out: 2404.37,486.01 2376.2,486.01 2376.2,457.74 2398.74,457.74
  pour cut-out: 2490.14,67.19 2490.14,15.14 2490,15 2472,15 2472,34.53 2481.02,43.55
  pour cut-out: 2610,1464 2653,1464 2651.05,1462.05 2651.05,1197.91 2648.62,1197.91 2617.71,1228.83 2617.71,1332.06 2611.42,1338.35
  pour cut-out: 2910,1464 2910,1441.33 2904.69,1441.33 2903.37,1440.01 2903,1440.38 2903,1465
  pour cut-out: 2561.13,556.71 2561.91,555.94 2615.8,555.94 2615.8,564.23 2613.58,562 2560,562
  pour cut-out: 1555,1390 1561,1384 2102,1384 2102,1198 2091,1187 1555,1187
  pour cut-out: 2304,1124 2305,1125 2330,1125 2330,1078.7 2332.73,1075.97 2301.27,1075.97
  pour cut-out: 2569.02,379.98 2596.02,379.98 2597,379 2594.98,376.98 2594.98,354.02 2569.34,354.02 2569.22,353.89
  pour cut-out: 350.43,616.62 350.5,616.69 350.5,685.02 353.98,685.02 366.79,672.21 366.79,637.21
  pour cut-out: 2176.61,165.75 2176.61,320.97 2235.21,262.37 2235.21,196.74 2204.71,166.24 2197.79,166.24
  pour cut-out: 2708,663 2708,574 2707,573 2708.28,571.72 2782.41,571.72
  text ".Layer_Name" at 577,-868.49 h60
Signal Layer 3:
  pour cut-out: 1971,1469 1971,1119 1970,1118 1996,1092 2620,1092 2620,1466 2622,1468
  pour cut-out: 2613,15 2610,18 2610,85 2552.58,27.58 2549.9,27.58 2549.9,18.9 2546,15
  pour cut-out: 1377.95,225.5 1378.71,224.75 1406.05,224.75 1406.05,204.05 1402.77,200.77 1378.77,200.77
  pour cut-out: 1347,765 1373,765 1374.02,763.98 1374.02,740.58 1346.37,740.58 1345.2,741.76
  pour cut-out: 1114.23,1255.23 939.21,1080.21 934.21,1080.21 934.21,700.79 965,670 1195,670 1195,972.42 1195.79,973.21 1119.76,1049.24 1119.76,1242.7
  pour cut-out: 506.13,317.01 507.17,315.98 743.18,315.98 743.18,173.82 742,175 505,175
  pour cut-out: 2050,1033 2050,1010 2051,1009 2050.02,1008.02 2024.02,1008.02 2024.02,1034.02 2025,1035
  pour cut-out: 1948,733 1950.98,735.98 1972.98,735.98 1972.98,715.43 1978.1,710.31 1968.62,700.83 1944.17,700.83
  pour cut-out: 1951,548 1971.94,548 1972.97,546.97 1971,545 1971,518 1949,518 1947,520
  pour cut-out: 2158,643 2159,642 2184,642 2184,616.05 2179.95,612 2157,612
  pour cut-out: 2126.47,869.15 2126.47,846.15 2131.77,840.85 2136.85,845.93 2154.25,845.93 2154.25,864.25 2156,866
  pour cut-out: 2492.48,976.48 2492.48,295.48 2479,282 2291,282
  pour cut-out: 759.54,1003.26 786.3,1003.26 786.79,1002.76 786,1001.97 786,979 761,979 760,980
  pour cut-out: 1157.8,1011.2 1233.78,1011.2 1195.79,973.21
  pour cut-out: 552,1100 553,1101 743,1101 743,1000 736,993 552,993
  pour cut-out: 2301.96,969.89 2331.94,969.89 2332.31,969.52 2329,966.2 2329,947 2304,947 2303,948
Bottom Layer:
  pour cut-out: 2239,1298 2241,1296 2241,1268 2336,1268 2334,1270 2334,1298 2332,1300
  pour cut-out: 1936,1464 1938.32,1461.68 1938.32,1299.81 1941.81,1299.81 2079,1437 2072,1444 2072,1466
  pour cut-out: 510,377 667,377 667,357 670,354 510,354
  pour cut-out: 645,307 870,307 866.8,303.8 866.8,279.22 855.58,268 640,268
  pour cut-out: 2037,674 2099,674 2098,673 2098,618 2040.15,618 2036.79,614.64
  pour cut-out: 2358,546 2422,546 2422,511 2358,511
  pour cut-out: 2744.02,532.98 2769.98,532.98 2771,531.95 2771,509 2746,509 2744.02,507.02
  pour cut-out: 1970,1022 1971,1021 2054.33,1021 2054.33,883.51 2049.61,878.79 2044.4,884 1977,884
  pour cut-out: 2013,893 2188,893 2190,891 2181.5,882.5 2181.5,764.6 2029.85,764.6 2020,754.75
  pour cut-out: 1316.25,329 1316.5,328.75 1316.5,225.5 1380.5,225.5 1383.75,222.25 1383.75,318.8
  pour cut-out: 1393,1142 1393,1198 1434,1239 1438,1235 1678.33,1235 1678.33,1134.8 1677.54,1134
  pour cut-out: 1379.81,733.73 1382.07,735.99 1429.63,735.99 1429.63,657.47 1437.91,649.2 1373.16,649.2
  pour cut-out: 1474,1068 1474,1022 1478,1018 1530,1018 1530,1066 1526,1070
  pour cut-out: 1673.26,1317.26 1938.32,1317.26 1938.32,1295.32 1748,1105 1739.01,1113.99 1667.63,1113.99
  pour cut-out: 481.99,295.37 481.99,14.99 482,15 593,15 593,303 578,318
  pour cut-out: 2578.73,300.19 2578.73,316.73 2579,317 2528,317 2528,309.26 2537.07,300.19
  text ".Layer_Name" at 577,-868.49 h60

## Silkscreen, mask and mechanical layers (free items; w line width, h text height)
Top Overlay:
  rectangle: 1632,21 1905,175
  text "C2000 EMIF Daughter Card  REV: E1" at 502,61 h72.83
  text ".Layer_Name" at 577,-868.49 h60
Bottom Overlay:
  text ".Layer_Name" at 577,-868.49 h60
Top Paste:
  text ".Layer_Name" at 577,-868.49 h60
Bottom Paste:
  text ".Layer_Name" at 577,-868.49 h60
Top Solder:
  text ".Layer_Name" at 577,-868.49 h60
  text ".Layer_Name" at 577,-868.49 h60
Bottom Solder:
  text ".Layer_Name" at 577,-868.49 h60
Drill Guide:
  text ".Layer_Name" at 577,-868.49 h60
M1 Board Outline:
  the board outline again, w10
  text ".Layer_Name" at 577,-868.49 h60
M2 Board Dimensions:
  rectangle: 0,-285 125,-160
  rectangle: 125,-410 500,-285
  lines w7: 0,-285 1000,-285 ; 125,-410 125,-160 ; 250,-410 250,-160 ; 500,-410 500,-160 ; 750,-410 750,-160 ; 0,-410 1000,-410 1000,-160 0,-160 0,-410
  text ".Layer_Name" at 577,-868.49 h60
M3 3D STEP Top:
  text ".Layer_Name" at 577,-868.49 h60
M4 3D STEP Bottom:
  text ".Layer_Name" at 577,-868.49 h60
M5 Assembly Top:
  lines w10: -292,-940.17 6308,-940.17 ; -292,-736.83 6310,-736.83 ; -292,-533.5 -292,-1143.5 3713,-1143.5 6310,-1143.5 6310,-533.5 -291.5,-533.5 -291.5,-1143.5 1284,-1143.5 ; 2173,-1143.5 2173,-533.5 ; 3440,-736.83 3440,-533.5 ; 4280,-736.83 4280,-533.5 ; 4902,-1150 4902,-947.17
  text "COMPONENTS MARKED 'DNP' SHOULD NOT BE POPULATED." at 1153.5,-328.5 h60
  text "ASSEMBLY VARIANT:" at 1153,-444 h60
  text ".VariantName" at 2189,-444 h60
  text "PCB VIEWED FROM TOP SIDE" at -228.5,-665.67 h60
  text "BOARD #:" at 2248,-665.67 h60
  text ".PRJ_Number" at 2793.5,-665.67 h60
  text "REV:" at 3638,-665.67 h60
  text ".PCB_Rev" at 3929.5,-665.67 h60
  text "SVN REV:" at 4476,-665.67 h60
  text ".VersionControl_RevNumber" at 4982,-665.67 h60
  text "TID #:" at 2248,-869 h60
  text ".TID" at 2793.5,-869 h60
  text "PLOT NAME =" at -228.5,-1074.34 h60
  text ".plot_File_Name" at 577,-1074.34 h60
  text "GENERATED    :" at 2250,-1074.34 h60
  text ".Print_Date" at 3119.5,-1074.34 h60
  text ".Print_Time" at 3848.5,-1074.34 h60
  text "TEXAS INSTRUMENTS" at 5113,-1074.34 h60
M6 Assembly Bottom:
  lines w10: -292.5,-737.33 6309.5,-737.33 ; -290.5,-940.67 6309.5,-940.67 ; 1115.5,-1150.5 1115.5,-947.67 ; 1737.5,-737.33 1737.5,-534 ; 2577.5,-737.33 2577.5,-534 ; 3844.5,-1144 3844.5,-534 ; 4733.5,-1144 6309,-1144 6309,-534 -292.5,-534 -292.5,-1144 2304.5,-1144 6309.5,-1144 6309.5,-534
  text "COMPONENTS MARKED 'DNP' SHOULD NOT BE POPULATED." at 6102,-328 h60
  text ".VariantName" at 5058,-444 h60
  text "ASSEMBLY VARIANT:" at 6097,-444 h60
  text ".VersionControl_RevNumber" at 1035.5,-666.17 h60
  text "SVN REV:" at 1541.5,-666.17 h60
  text ".PCB_Rev" at 2088,-666.17 h60
  text "REV:" at 2379.5,-666.17 h60
  text ".PRJ_Number" at 3224,-666.17 h60
  text "BOARD #:" at 3769.5,-666.17 h60
  text "PCB VIEWED FROM BOTTOM SIDE" at 6246,-666.17 h60
  text ".TID" at 3224,-869.5 h60
  text "TID #:" at 3769.5,-869.5 h60
  text "TEXAS INSTRUMENTS" at 904.5,-1074.84 h60
  text ".Print_Time" at 2169,-1074.84 h60
  text ".Print_Date" at 2898,-1074.84 h60
  text "GENERATED    :" at 3767.5,-1074.84 h60
  text ".plot_File_Name" at 5440.5,-1074.84 h60
  text "PLOT NAME =" at 6246,-1074.84 h60
M9 Title Sheet:
  drawing of 57 lines, arcs and shapes, not listed
  text "1" at 739.84,8026.5 h70
  text "2" at 3235.5,8026.5 h70
  text "3" at 5724.84,8026.5 h70
  text "4" at 8231.51,8026.5 h70
  text "5" at 10730.5,8026.5 h70
  text "6" at 13235.5,8026.5 h70
  text "A" at -416.5,6883.5 h70
  text "A" at 14383.5,6883.5 h70
  text "B" at -416.5,4503.5 h70
  text "B" at 14383.5,4503.5 h70
  text "C" at -416.5,2128.5 h70
  text "C" at 14383.5,2128.5 h70
  text "PROJECT TITLE:" at 11343.5,267.5 h45
  text ".PRJ_Title" at 11393.5,134.17 h70
  text "DESIGNED FOR:" at 11343.5,-33.5 h45
  text ".PRJ_Customer" at 11393.5,-173.5 h70
  text "D" at -416.5,-241.5 h70
  text "D" at 14383.5,-241.5 h70
  text "FILE NAME:" at 11343.5,-333.5 h45
  text ".PCB_File_Name_No_Path" at 11393.5,-453.5 h70
  text "Texas Instruments (TI) and/or its licensors do not warrant the accuracy or completeness of this specification" at 6374,-615.34 h45
  text "ENGINEER:" at 11343.5,-623.5 h45
  text "LAYOUT BY:" at 12848.5,-623.5 h45
  text "or any information contained therein. TI and/or its licensors do not warrant that this design will meet" at 6329.01,-728 h45
  text ".PRJ_Engineer" at 11393.5,-778.49 h70
  text ".PCB_Layout" at 12899,-778.49 h70
  text "the specifications, will be suitable for your application or fit for any particular purpose, or will operate in" at 6329.01,-840.67 h45
  text ".Layer_Name" at 577,-868.49 h60
  text "ALTIUM DESIGNER VERSION:" at 12848.5,-933.5 h45
  text "an implementation. TI and/or its licensors do not warrant that the design is production worthy. You should" at 6329.01,-953.33 h45
  text "completely validate and test your design implementation to confirm the system functionality for your application." at 6374,-1066 h45
  text ".print_Scale" at 11393.5,-1066.83 h70
  text ".Application_BuildNumber" at 12899,-1066.83 h70
  text "1" at 739.84,-1273.5 h70
  text "2" at 3235.5,-1273.5 h70
  text "3" at 5724.84,-1273.5 h70
  text "4" at 8231.51,-1273.5 h70
  text "5" at 10730.5,-1273.5 h70
  text "6" at 13235.5,-1273.5 h70
M10 Fab Notes:
  drawing of 173 lines, arcs and shapes, not listed
  text "DESIGN INFORMATION" at 12378.02,6191 h60
  text "MIN. TRACK WIDTH:" at 11733.46,6011 h60
  text "6" at 12829.7,6011 h60
  text "MIL" at 12984.46,6011 h60
  text "MIN. CLEARANCE:" at 11733.46,5879 h60
  text "0.2" at 12769.7,5879 h60
  text "mm" at 12984.46,5879 h60
  text "MIN. VIA PAD SIZE:" at 11733.46,5747 h60
  text "24" at 12799.71,5747 h60
  text "MIL" at 12984.46,5747 h60
  text "0.05mm (2MIL)" at 12428.46,5605.29 h60
  text "MINIMUM ANNULAR RING" at 11404.23,5601 h60
  text "EXTERNAL" at 13136.46,5601 h60
  text "PER" at 11604.23,5483 h60
  text "IPC-D-275 CLASS 2 LEVEL C" at 11824.23,5483 h60
  text "MIL, HOLES" at 13312.46,5370.71 h60
  text "+/-" at 12920,5370 h60
  text "+/-" at 13774,5370 h60
  text "REGISTRATION TOLERANCES:" at 11404.23,5365 h60
  text "METAL" at 12604,5365 h60
  text "5" at 13180.2,5365 h60
  text "3" at 14013.2,5365 h60
  text "MIL" at 14129.46,5365 h60
  text "+/-" at 13774,5252 h60
  text "HOLE SIZE TOLERANCE (UNLESS OTHERWISE SPECIFIED):" at 11404.23,5247 h60
  text "3" at 14013.2,5247 h60
  text "MIL" at 14129.46,5247 h60
  text "MATERIAL:" at 11329.46,5037.54 h60
  text "FR-4 High Tg" at 12315.9,4897.21 h60
  text "FR-408" at 11750.46,4888.64 h60
  text "OTHER" at 13238.46,4888.64 h60
  text "X" at 12161,4885 h60
  text "62 MIL (1.6mm) +/-10%" at 12070.56,4725.92 h60
  text "THICKNESS:" at 11404.23,4721.64 h60
  text "X" at 11942.4,4721.64 h60
  text "OTHER" at 13355.46,4721.64 h60
  text "TOLERANCE:" at 11404.23,4563.64 h60
  text "X" at 12243.53,4563.64 h60
  text "ANSI IPC-6012 TYPE 3 CLASS 2" at 12430.48,4563.64 h60
  text "OTHER +/-" at 12430.46,4407.64 h60
  text "BOW & TWIST:" at 11404.23,4250.64 h60
  text "X" at 12243.53,4250.64 h60
  text "ANSI IPC-6012 TYPE 3 CLASS 2" at 12430.48,4250.64 h60
  text "OTHER +/-" at 12430.46,4092.13 h60
  text "DRILLING:" at 11329.46,3953.64 h60
  text "REFERENCE:" at 11404.23,3836.64 h60
  text "X" at 12052.46,3836.64 h60
  text "AS SHOWN" at 12239.46,3836.64 h60
  text "X" at 12953.46,3836.64 h60
  text "NC_DRILL FILES" at 13090.46,3836.64 h60
  text "PTH COPPER THICKNESS:" at 11404.23,3678.64 h60
  text "X" at 12534.46,3678.64 h60
  text "20-30 um" at 12671.46,3678.64 h60
  text "OTHER" at 13388.46,3678.64 h60
  text "BOARD FINISH:" at 11329.46,3519.64 h60
  text "SILKSCREEN:" at 11484.68,3401.64 h60
  text "X" at 12433.46,3401.64 h60
  text "TOP" at 12559.46,3401.64 h60
  text "X" at 12943.46,3401.64 h60
  text "BOTTOM" at 13070.46,3401.64 h60
  text "SILKSCREEN COLOR:" at 11484.68,3234.64 h60
  text "X" at 12432.42,3234.64 h60
  text "WHITE" at 12559.46,3234.64 h60
  text "OTHER" at 13070.46,3234.64 h60
  text "X" at 12563.42,3075.44 h60
  text "GREEN" at 12690.46,3075.44 h60
  text "OTHER" at 13308.46,3075.44 h60
  text "SOLDER RESIST COLOR:" at 11484.68,3064.64 h60
  text "X" at 12563.42,2905.44 h60
  text "MATTE" at 12690.46,2905.44 h60
  text "SEMI-GLOSS" at 13308,2904.8 h60
  text "IMMERSION GOLD (ENIG)" at 12390.46,2716.92 h60
  text "ENEPIG" at 13728,2713.64 h60
  text "SURFACE FINISH:" at 11329.46,2712.64 h60
  text "X" at 12203.51,2712.64 h60
  text "IMM. TIN/SILVER OR EQUIV" at 11659,2555.64 h60
  text "OTHER" at 13090.46,2555.64 h60
  text "ARRAY/PANEL:" at 11329.46,2376.64 h60
  text "CUT AND TRIM PER M1 BOARD OUTLINE" at 12390.46,2372.35 h60
  text "N.C. ROUTE" at 12390.46,2220.64 h60
  text "X" at 13069.46,2220.64 h60
  text "V. SCORE" at 13256.46,2220.64 h60
  text "CERTIFICATION:" at 11329.46,2083.64 h60
  text "MATERIALS AND WORKMANSHIP FOR ALL PCBS" at 12054.46,2083.64 h60
  text "TO MEET OR EXCEED THE REQUIREMENTS OF:" at 12054.46,1985.64 h60
  text "X" at 11680.96,1849.13 h60
  text "ANSI IPC-A-600F CLASS ->" at 11819.96,1849.13 h60
  text "X" at 13459.02,1849.13 h60
  text "2" at 13577.96,1849.14 h60
  text "1" at 13262.96,1847.64 h60
  text "3" at 13931.96,1847.64 h60
  text "X" at 12495.02,1689.64 h60
  text "RoHS" at 12631.96,1689.64 h60
  text "OTHER" at 13276.36,1689.64 h60
  text "PER ORDER" at 13673.42,1689.64 h60
  text "ALL BOARDS MUST MEET OR EXCEED UL94-V0 REQUIREMENTS." at 11357,1524 h60
  text "PCB MUST BEAR THE UL94V-0 UL REGISTERED MATERIAL ID NUMBER" at 11357,1404 h60
  text "ADDITIONAL REQUIREMENTS:" at 11329.46,1230.64 h60
  text "MICROSECTION:" at 11404.23,1115.64 h60
  text "YES" at 12309.96,1115.64 h60
  text "REQUIRED" at 13171.46,959.49 h60
  text "BARE BOARD ELEC. TEST:" at 11404.23,956.64 h60
  text "NONE" at 12709.96,956.64 h60
  text "X" at 13044.46,956.64 h60
  text "PER ORDER" at 13763.46,956.64 h60
  text ".Layer_Name" at 577,-868.49 h60
M11 Gerber Information:
  lines w10: -292,-940.17 6308,-940.17 ; -292,-736.83 6310,-736.83 ; -292,-533.5 -292,-1143.5 3713,-1143.5 6310,-1143.5 6310,-533.5 -291.5,-533.5 -291.5,-1143.5 1284,-1143.5 ; 2173,-1143.5 2173,-533.5 ; 3440,-736.83 3440,-533.5 ; 4280,-736.83 4280,-533.5 ; 4902,-1150 4902,-947.17
  text "ALL ARTWORK VIEWED FROM TOP SIDE" at -228.5,-665.67 h60
  text "BOARD #:" at 2248,-665.67 h60
  text ".PRJ_Number" at 2793.5,-665.67 h60
  text "REV:" at 3638,-665.67 h60
  text ".PCB_Rev" at 3929.5,-665.67 h60
  text "SVN REV:" at 4476,-665.67 h60
  text ".VersionControl_RevNumber" at 4982,-665.67 h60
  text "LAYER NAME =" at -228.5,-868.49 h60
  text "TID #:" at 2248,-869 h60
  text ".TID" at 2793.5,-869 h60
  text "PLOT NAME =" at -228.5,-1074.34 h60
  text ".plot_File_Name" at 577,-1074.34 h60
  text "GENERATED    :" at 2250,-1074.34 h60
  text ".Print_Date" at 3119.5,-1074.34 h60
  text ".Print_Time" at 3848.5,-1074.34 h60
  text "TEXAS INSTRUMENTS" at 5113,-1074.34 h60
M12 Stackup:
  drawing of 399 lines, arcs and shapes, not listed
  text "Layer" at 6632.35,7699 h60
  text "Name" at 7042.26,7699 h60
  text "Material" at 7982,7699 h60
  text "Thickness" at 8841.77,7699 h60
  text "Constant" at 9491.6,7699 h60
  text "Board Layer Stack" at 10061.46,7699 h60
  text "1" at 6632.35,7579 h60
  text "Top Overlay" at 7042.26,7579 h60
  text "2" at 6632.35,7459 h60
  text "Top Solder" at 7042.26,7459 h60
  text "Solder Resist" at 7982,7459 h60
  text "0.50mil" at 8841.77,7459 h60
  text "3.5" at 9491.6,7459 h60
  text "3" at 6632.35,7339 h60
  text "Top Layer" at 7042.26,7339 h60
  text "Copper" at 7982,7339 h60
  text "1.40mil" at 8841.77,7339 h60
  text "4" at 6632.35,7219 h60
  text "Dielectric 1" at 7042.26,7219 h60
  text "FR-4" at 7982,7219 h60
  text "7.00mil" at 8841.77,7219 h60
  text "4.2" at 9491.6,7219 h60
  text "5" at 6632.35,7099 h60
  text "Signal Layer 1" at 7042.26,7099 h60
  text "Copper" at 7982,7099 h60
  text "1.40mil" at 8841.77,7099 h60
  text "6" at 6632.35,6979 h60
  text "Dielectric 2" at 7042.26,6979 h60
  text "FR-4" at 7982,6979 h60
  text "14.00mil" at 8841.77,6979 h60
  text "4.2" at 9491.6,6979 h60
  text "7" at 6632.35,6859 h60
  text "Signal Layer 2" at 7042.26,6859 h60
  text "Copper" at 7982,6859 h60
  text "1.40mil" at 8841.77,6859 h60
  text "8" at 6632.35,6739 h60
  text "Dielectric 4" at 7042.26,6739 h60
  text "FR-4" at 7982,6739 h60
  text "11.00mil" at 8841.77,6739 h60
  text "4.2" at 9491.6,6739 h60
  text "9" at 6632.35,6619 h60
  text "Signal Layer 3" at 7042.26,6619 h60
  text "Copper" at 7982,6619 h60
  text "1.40mil" at 8841.77,6619 h60
  text "10" at 6632.35,6499 h60
  text "Dielectric 5" at 7042.26,6499 h60
  text "FR-4" at 7982,6499 h60
  text "14.00mil" at 8841.77,6499 h60
  text "4.2" at 9491.6,6499 h60
  text "11" at 6632.35,6379 h60
  text "Signal Layer 4" at 7042.26,6379 h60
  text "Copper" at 7982,6379 h60
  text "1.40mil" at 8841.77,6379 h60
  text "12" at 6632.35,6259 h60
  text "Dielectric 3" at 7042.26,6259 h60
  text "FR-4" at 7982,6259 h60
  text "7.00mil" at 8841.77,6259 h60
  text "4.2" at 9491.6,6259 h60
  text "13" at 6632.35,6139 h60
  text "Bottom Layer" at 7042.26,6139 h60
  text "Copper" at 7982,6139 h60
  text "1.40mil" at 8841.77,6139 h60
  text "14" at 6632.35,6019 h60
  text "Bottom Solder" at 7042.26,6019 h60
  text "Solder Resist" at 7982,6019 h60
  text "0.50mil" at 8841.77,6019 h60
  text "3.5" at 9491.6,6019 h60
  text "15" at 6632.35,5899 h60
  text "Bottom Overlay" at 7042.26,5899 h60
  text ".Layer_Name" at 577,-868.49 h60
M13 Component Bodies Top:
  text ".Layer_Name" at 577,-868.49 h60
M14 Component Bodies Bottom:
  text ".Layer_Name" at 577,-868.49 h60
M15 Courtyards Top:
  text ".Layer_Name" at 577,-868.49 h60
M16 Courtyards Bottom:
  text ".Layer_Name" at 577,-868.49 h60
Drill Drawing:
  circle w10: c5348.65,3094.97 r22.05
  lines w10: 5326.6,3172.13 5370.7,3172.13 5370.7,3216.22 5326.6,3216.22 5326.6,3172.13 ; 5326.6,3282.36 5337.63,3282.36 5348.65,3271.34 5359.68,3282.36 5370.7,3282.36 5359.68,3293.39 5370.7,3304.41 5359.68,3304.41 5348.65,3315.43 5337.63,3304.41 5326.6,3304.41 5337.63,3293.39 5326.6,3282.36
  lines w12: 5286,3043.16 8395.46,3043.16 ; 5286,3340.79 8395.46,3340.79 ; 5601.13,2943.94 5601.13,3440 ; 5917.88,2943.94 5917.88,3440 ; 6538.9,2943.94 6538.9,3440 ; 6782.83,2943.94 6782.83,3440 ; 7142.73,2943.94 7142.73,3440 ; 7851.88,2943.94 7851.88,3440 ; 5286,2943.94 8395.46,2943.94 8395.46,3440 5286,3440 5286,2943.94
  text "Symbol" at 5345.53,3370.55 h72
  text "Quantity" at 5630.9,3370.55 h72
  text "Finished Hole Size" at 5947.64,3370.55 h72
  text "Plated" at 6568.66,3370.55 h72
  text "Hole Type" at 6812.59,3370.55 h72
  text "Drill Layer Pair" at 7172.49,3370.55 h72
  text "Hole Tolerance" at 7881.64,3370.55 h72
  text "3" at 5630.9,3271.34 h60
  text "98.43mil (2.500mm)" at 5947.64,3271.34 h60
  text "NPTH" at 6568.66,3271.34 h60
  text "Round" at 6812.59,3271.34 h60
  text "Top Layer - Bottom Layer" at 7172.49,3271.34 h60
  text "205" at 5630.9,3172.13 h60
  text "10.00mil (0.254mm)" at 5947.64,3172.13 h60
  text "PTH" at 6568.66,3172.13 h60
  text "Round" at 6812.59,3172.13 h60
  text "Top Layer - Bottom Layer" at 7172.49,3172.13 h60
  text "2" at 5630.9,3072.92 h60
  text "25.00mil (0.635mm)" at 5947.64,3072.92 h60
  text "PTH" at 6568.66,3072.92 h60
  text "Round" at 6812.59,3072.92 h60
  text "Top Layer - Bottom Layer" at 7172.49,3072.92 h60
  text "210 Total" at 5630.9,2973.71 h60
  text ".Layer_Name" at 577,-868.49 h60
Mechanical 17:
  text ".Layer_Name" at 577,-868.49 h60
Mechanical 18:
  text ".Layer_Name" at 577,-868.49 h60
Mechanical 19:
  text ".Layer_Name" at 577,-868.49 h60

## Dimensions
0,-410 to 1000,-410 on M2 Board Dimensions
0,0 to 0,1480 on M2 Board Dimensions
0,-10 to 3000,0 on M2 Board Dimensions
